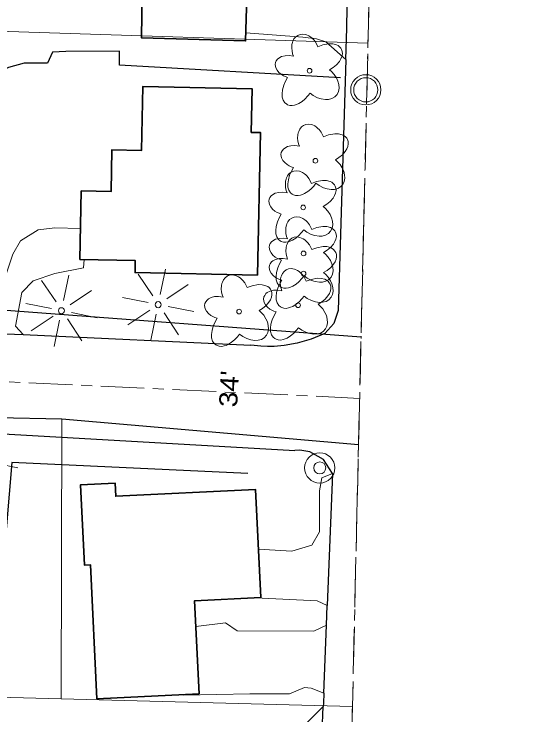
# Model space of a CAD drawing. Extents: x -861682 to -858969, y -1797841 to -1795153.
# Drawn here: x -859141.7 to -858974.4, y -1797575.9 to -1797344.4 of the extents above; entities that cross this region are included whole.
import ezdxf

# ---------------------------------------------------------------- set-up
doc = ezdxf.new("R2010")
doc.units = 0
doc.header["$LTSCALE"] = 2.4
doc.linetypes.add('DOT_DASHED', pattern=[7.7, 5, -1.2, 0.3, -1.2])
doc.linetypes.add('LONG_DASH_SHORT_DASH', pattern=[9.9, 6, -1.2, 1.5, -1.2])
for name, color, linetype, lineweight in [('10', 7, 'Continuous', 25), ('11', 7, 'Continuous', 13), ('12', 7, 'Continuous', 35), ('14', 7, 'Continuous', 25), ('17', 7, 'Continuous', 13), ('30', 7, 'Continuous', 13), ('31', 7, 'Continuous', 13), ('32', 7, 'LONG_DASH_SHORT_DASH', 13), ('36', 7, 'Continuous', 13), ('42', 7, 'Continuous', 25), ('61', 7, 'Continuous', 13)]:
    doc.layers.add(name, color=color, linetype=linetype, lineweight=lineweight)
doc.layers.add('43', color=7, linetype='Continuous')

msp = doc.modelspace()

# ---------------------------------------------------------------- linework, layer by layer
at = {"layer": '10'}
for p, q in [((-859031.959, -1797359.387), (-859034.465, -1797442.355)), ((-859150.644, -1797449.718), (-859138.672, -1797450.273)), ((-859138.672, -1797450.273), (-859063.397, -1797453.762)), ((-859160.676, -1797482.211), (-859048.845, -1797488.56)), ((-859036.441, -1797496.144), (-859038.139, -1797539.752)), ((-859040.841, -1797602.889), (-859039.445, -1797573.069))]:
    msp.add_line(p, q, dxfattribs=at)
for points in [[(-859031.959, -1797359.387), (-859031.647, -1797349.046), (-859031.317, -1797328.075), (-859030.076, -1797249.095)], [(-859034.465, -1797442.355), (-859035.905, -1797446.557), (-859038.878, -1797449.857)], [(-859038.878, -1797449.857), (-859043.482, -1797451.799), (-859048.07, -1797453.13), (-859052.41, -1797453.888), (-859055.704, -1797454.154), (-859057.908, -1797454.187), (-859060.11, -1797454.104), (-859063.397, -1797453.762)], [(-859036.441, -1797496.144), (-859039.41, -1797491.565), (-859043.901, -1797488.956), (-859047.157, -1797488.451), (-859048.845, -1797488.56)], [(-859039.268, -1797568.71), (-859038.391, -1797546.199), (-859038.139, -1797539.752)], [(-859039.268, -1797568.71), (-859039.398, -1797572.048), (-859039.445, -1797573.069)]]:
    msp.add_lwpolyline(points, dxfattribs=at)
at = {"layer": '11'}
for points in [[(-859065.049, -1797350.603), (-859046.217, -1797351.984), (-859041.666, -1797352.583), (-859038.606, -1797353.6), (-859031.959, -1797359.387)], [(-859119.67, -1797415.266), (-859128.165, -1797415.055), (-859133.683, -1797415.671), (-859139.516, -1797419.326), (-859142.077, -1797423.661), (-859144.873, -1797432.314), (-859147.655, -1797444.888), (-859150.644, -1797449.718)], [(-859118.462, -1797425.472), (-859118.655, -1797428.258), (-859128.166, -1797430.062), (-859135.329, -1797432.552), (-859139.035, -1797436.338), (-859141.126, -1797447.52), (-859138.672, -1797450.273)], [(-859060.863, -1797521.16), (-859049.801, -1797521.842), (-859043.273, -1797519.823), (-859040.739, -1797515.423), (-859040.666, -1797501.822), (-859039.896, -1797497.6), (-859036.441, -1797496.144)], [(-859061.99, -1797537.199), (-859041.503, -1797538.157), (-859038.139, -1797539.752)], [(-859081.578, -1797546.666), (-859071.713, -1797545.472), (-859067.862, -1797548.131), (-859042.601, -1797548.221), (-859038.391, -1797546.199)], [(-859085.546, -1797569.344), (-859063.761, -1797568.966), (-859050.597, -1797568.885), (-859045.596, -1797566.835), (-859043.41, -1797567.034), (-859039.268, -1797568.71)], [(-859309.938, -1797594.48), (-859309.62, -1797592.433), (-859289.953, -1797586.603), (-859281.507, -1797585.021), (-859271.667, -1797583.556), (-859251.167, -1797579.721), (-859236.104, -1797579.853), (-859215.218, -1797579.069), (-859192.063, -1797577.66), (-859174.024, -1797577.051), (-859160.73, -1797577.456), (-859109.405, -1797580.619), (-859083.978, -1797581.644), (-859068.807, -1797581.049), (-859054.386, -1797580.217), (-859044.812, -1797578.418), (-859039.445, -1797573.069)]]:
    msp.add_lwpolyline(points, dxfattribs=at)
at = {"layer": '12'}
for points in [[(-859051.474, -1797316.259), (-859063.256, -1797272.71), (-859087.25, -1797279.202), (-859086.157, -1797283.24), (-859122.212, -1797292.999), (-859111.518, -1797332.511), (-859099.235, -1797329.186), (-859099.5, -1797352.252), (-859065.127, -1797353.254), (-859064.383, -1797327.746), (-859085.787, -1797327.122), (-859085.724, -1797325.529)], [(-859061.133, -1797430.656), (-859060.143, -1797383.561), (-859063.248, -1797383.496), (-859062.946, -1797369.051), (-859099.061, -1797368.296), (-859099.503, -1797389.42), (-859109.291, -1797389.215), (-859109.58, -1797403.01), (-859119.41, -1797402.804), (-859119.884, -1797425.443), (-859101.577, -1797425.826), (-859101.66, -1797429.806)], [(-859114.254, -1797570.531), (-859116.403, -1797526.301), (-859118.358, -1797526.396), (-859119.648, -1797499.847), (-859108.241, -1797499.293), (-859108.028, -1797503.679), (-859061.821, -1797501.435), (-859060.089, -1797537.107), (-859081.991, -1797538.17), (-859080.5, -1797568.893)]]:
    msp.add_lwpolyline(points, close=True, dxfattribs=at)
at = {"layer": '14'}
for points in [[(-859033.708, -1797365.447), (-859106.737, -1797361.329), (-859106.769, -1797356.675), (-859124.551, -1797356.727), (-859128.899, -1797356.969), (-859130.59, -1797360.624), (-859138.271, -1797360.661), (-859143.419, -1797362), (-859148.483, -1797364.556), (-859153.142, -1797368.793), (-859157.373, -1797374.905), (-859159.7, -1797382.153), (-859162.796, -1797394.134), (-859163.901, -1797400.693)], [(-859064.385, -1797496.166), (-859142.416, -1797492.569), (-859148.648, -1797565.786)]]:
    msp.add_lwpolyline(points, dxfattribs=at)
at = {"layer": '17'}
for p, q in [((-859093.349, -1797437.028), (-859091.623, -1797428.628)), ((-859125.308, -1797439.034), (-859123.582, -1797430.634)), ((-859095.809, -1797437.488), (-859100.599, -1797430.36)), ((-859127.768, -1797439.494), (-859132.558, -1797432.366)), ((-859091.149, -1797438.428), (-859084.053, -1797433.688)), ((-859123.108, -1797440.434), (-859116.012, -1797435.694)), ((-859097.309, -1797439.688), (-859105.771, -1797438.014)), ((-859129.268, -1797441.694), (-859137.73, -1797440.02)), ((-859090.709, -1797440.948), (-859082.229, -1797442.672)), ((-859122.668, -1797442.954), (-859114.188, -1797444.678)), ((-859096.769, -1797442.188), (-859103.995, -1797447.044)), ((-859096.389, -1797452.148), (-859094.709, -1797443.548)), ((-859092.049, -1797443.088), (-859087.249, -1797450.302)), ((-859128.728, -1797444.194), (-859135.954, -1797449.05)), ((-859128.348, -1797454.154), (-859126.668, -1797445.554)), ((-859124.008, -1797445.094), (-859119.208, -1797452.308)), ((-859148.831, -1797492.523), (-859140.351, -1797494.247))]:
    msp.add_line(p, q, dxfattribs=at)
for points in [[(-859043.8, -1797370.522), (-859042.758, -1797371.29), (-859041.352, -1797372.012), (-859040.104, -1797372.418), (-859038.732, -1797372.614), (-859037.714, -1797372.564), (-859036.57, -1797372.274), (-859035.638, -1797371.722), (-859034.898, -1797370.934), (-859034.43, -1797369.976), (-859034.22, -1797368.898), (-859034.324, -1797367.702), (-859034.614, -1797366.53), (-859035.1, -1797365.47), (-859035.822, -1797364.326), (-859036.688, -1797363.406), (-859037.37, -1797362.794), (-859036.188, -1797362.078), (-859035.042, -1797361.13), (-859034.122, -1797360.038), (-859033.6, -1797359.182), (-859033.268, -1797358.368), (-859033.122, -1797357.552), (-859033.162, -1797356.79), (-859033.378, -1797356.11), (-859033.636, -1797355.658), (-859034.056, -1797355.184), (-859034.516, -1797354.83), (-859035.082, -1797354.54), (-859036.318, -1797354.212), (-859037.56, -1797354.178), (-859039.606, -1797354.554), (-859041.266, -1797355.192), (-859042.056, -1797353.614), (-859042.71, -1797352.8), (-859043.122, -1797352.398), (-859043.586, -1797351.998), (-859044.188, -1797351.606), (-859045.192, -1797351.174), (-859046.206, -1797351.004), (-859047.094, -1797351.104), (-859047.894, -1797351.438), (-859048.56, -1797351.924), (-859049.12, -1797352.63), (-859049.47, -1797353.386), (-859049.628, -1797353.824), (-859049.796, -1797354.5), (-859049.848, -1797355.662), (-859049.776, -1797356.56), (-859049.564, -1797357.522), (-859049.28, -1797358.328), (-859050.722, -1797358.096), (-859052.08, -1797358.146), (-859053.238, -1797358.432), (-859054.126, -1797358.93), (-859054.566, -1797359.274), (-859055, -1797359.84), (-859055.238, -1797360.374), (-859055.362, -1797361.052), (-859055.16, -1797362.156), (-859054.704, -1797362.968), (-859054.08, -1797363.73), (-859053.302, -1797364.346), (-859052.604, -1797364.77), (-859051.94, -1797365.058), (-859051.212, -1797365.296), (-859051.896, -1797366.508), (-859052.518, -1797367.876), (-859052.914, -1797369.378), (-859053.048, -1797370.712), (-859053.038, -1797371.802), (-859052.704, -1797372.82), (-859052.182, -1797373.666), (-859051.624, -1797374.102), (-859051.238, -1797374.348), (-859050.504, -1797374.572), (-859049.71, -1797374.584), (-859048.94, -1797374.46), (-859048.28, -1797374.248), (-859047.536, -1797373.926), (-859046.46, -1797373.246), (-859045.498, -1797372.46), (-859044.542, -1797371.442), (-859043.796, -1797370.532)], [(-859041.865, -1797400.271), (-859040.823, -1797401.039), (-859039.417, -1797401.761), (-859038.169, -1797402.167), (-859036.797, -1797402.363), (-859035.779, -1797402.313), (-859034.635, -1797402.023), (-859033.703, -1797401.471), (-859032.963, -1797400.683), (-859032.495, -1797399.725), (-859032.285, -1797398.647), (-859032.389, -1797397.451), (-859032.679, -1797396.279), (-859033.165, -1797395.219), (-859033.887, -1797394.075), (-859034.753, -1797393.155), (-859035.435, -1797392.543), (-859034.253, -1797391.827), (-859033.107, -1797390.879), (-859032.187, -1797389.787), (-859031.665, -1797388.931), (-859031.333, -1797388.117), (-859031.187, -1797387.301), (-859031.227, -1797386.539), (-859031.443, -1797385.859), (-859031.701, -1797385.407), (-859032.121, -1797384.933), (-859032.581, -1797384.579), (-859033.147, -1797384.289), (-859034.383, -1797383.961), (-859035.625, -1797383.927), (-859037.671, -1797384.303), (-859039.331, -1797384.941), (-859040.121, -1797383.363), (-859040.775, -1797382.549), (-859041.187, -1797382.147), (-859041.651, -1797381.747), (-859042.253, -1797381.355), (-859043.257, -1797380.923), (-859044.271, -1797380.753), (-859045.159, -1797380.853), (-859045.959, -1797381.187), (-859046.625, -1797381.673), (-859047.185, -1797382.379), (-859047.535, -1797383.135), (-859047.693, -1797383.573), (-859047.861, -1797384.249), (-859047.913, -1797385.411), (-859047.841, -1797386.309), (-859047.629, -1797387.271), (-859047.345, -1797388.077), (-859048.787, -1797387.845), (-859050.145, -1797387.895), (-859051.303, -1797388.181), (-859052.191, -1797388.679), (-859052.631, -1797389.023), (-859053.065, -1797389.589), (-859053.303, -1797390.123), (-859053.427, -1797390.801), (-859053.225, -1797391.905), (-859052.769, -1797392.717), (-859052.145, -1797393.479), (-859051.367, -1797394.095), (-859050.669, -1797394.519), (-859050.005, -1797394.807), (-859049.277, -1797395.045), (-859049.961, -1797396.257), (-859050.583, -1797397.625), (-859050.979, -1797399.127), (-859051.113, -1797400.461), (-859051.103, -1797401.551), (-859050.769, -1797402.569), (-859050.247, -1797403.415), (-859049.689, -1797403.851), (-859049.303, -1797404.097), (-859048.569, -1797404.321), (-859047.775, -1797404.333), (-859047.005, -1797404.209), (-859046.345, -1797403.997), (-859045.601, -1797403.675), (-859044.525, -1797402.995), (-859043.563, -1797402.209), (-859042.607, -1797401.191), (-859041.861, -1797400.281)], [(-859045.904, -1797415.666), (-859044.862, -1797416.434), (-859043.456, -1797417.156), (-859042.208, -1797417.562), (-859040.836, -1797417.758), (-859039.818, -1797417.708), (-859038.674, -1797417.418), (-859037.742, -1797416.866), (-859037.002, -1797416.078), (-859036.534, -1797415.12), (-859036.324, -1797414.042), (-859036.428, -1797412.846), (-859036.718, -1797411.674), (-859037.204, -1797410.614), (-859037.926, -1797409.47), (-859038.792, -1797408.55), (-859039.474, -1797407.938), (-859038.292, -1797407.222), (-859037.146, -1797406.274), (-859036.226, -1797405.182), (-859035.704, -1797404.326), (-859035.372, -1797403.512), (-859035.226, -1797402.696), (-859035.266, -1797401.934), (-859035.482, -1797401.254), (-859035.74, -1797400.802), (-859036.16, -1797400.328), (-859036.62, -1797399.974), (-859037.186, -1797399.684), (-859038.422, -1797399.356), (-859039.664, -1797399.322), (-859041.71, -1797399.698), (-859043.37, -1797400.336), (-859044.16, -1797398.758), (-859044.814, -1797397.944), (-859045.226, -1797397.542), (-859045.69, -1797397.142), (-859046.292, -1797396.75), (-859047.296, -1797396.318), (-859048.31, -1797396.148), (-859049.198, -1797396.248), (-859049.998, -1797396.582), (-859050.664, -1797397.068), (-859051.224, -1797397.774), (-859051.574, -1797398.53), (-859051.732, -1797398.968), (-859051.9, -1797399.644), (-859051.952, -1797400.806), (-859051.88, -1797401.704), (-859051.668, -1797402.666), (-859051.384, -1797403.472), (-859052.826, -1797403.24), (-859054.184, -1797403.29), (-859055.342, -1797403.576), (-859056.23, -1797404.074), (-859056.67, -1797404.418), (-859057.104, -1797404.984), (-859057.342, -1797405.518), (-859057.466, -1797406.196), (-859057.264, -1797407.3), (-859056.808, -1797408.112), (-859056.184, -1797408.874), (-859055.406, -1797409.49), (-859054.708, -1797409.914), (-859054.044, -1797410.202), (-859053.316, -1797410.44), (-859054, -1797411.652), (-859054.622, -1797413.02), (-859055.018, -1797414.522), (-859055.152, -1797415.856), (-859055.142, -1797416.946), (-859054.808, -1797417.964), (-859054.286, -1797418.81), (-859053.728, -1797419.246), (-859053.342, -1797419.492), (-859052.608, -1797419.716), (-859051.814, -1797419.728), (-859051.044, -1797419.604), (-859050.384, -1797419.392), (-859049.64, -1797419.07), (-859048.564, -1797418.39), (-859047.602, -1797417.604), (-859046.646, -1797416.586), (-859045.9, -1797415.676)], [(-859045.79, -1797430.871), (-859044.748, -1797431.639), (-859043.342, -1797432.361), (-859042.094, -1797432.767), (-859040.722, -1797432.963), (-859039.704, -1797432.913), (-859038.56, -1797432.623), (-859037.628, -1797432.071), (-859036.888, -1797431.283), (-859036.42, -1797430.325), (-859036.21, -1797429.247), (-859036.314, -1797428.051), (-859036.604, -1797426.879), (-859037.09, -1797425.819), (-859037.812, -1797424.675), (-859038.678, -1797423.755), (-859039.36, -1797423.143), (-859038.178, -1797422.427), (-859037.032, -1797421.479), (-859036.112, -1797420.387), (-859035.59, -1797419.531), (-859035.258, -1797418.717), (-859035.112, -1797417.901), (-859035.152, -1797417.139), (-859035.368, -1797416.459), (-859035.626, -1797416.007), (-859036.046, -1797415.533), (-859036.506, -1797415.179), (-859037.072, -1797414.889), (-859038.308, -1797414.561), (-859039.55, -1797414.527), (-859041.596, -1797414.903), (-859043.256, -1797415.541), (-859044.046, -1797413.963), (-859044.7, -1797413.149), (-859045.112, -1797412.747), (-859045.576, -1797412.347), (-859046.178, -1797411.955), (-859047.182, -1797411.523), (-859048.196, -1797411.353), (-859049.084, -1797411.453), (-859049.884, -1797411.787), (-859050.55, -1797412.273), (-859051.11, -1797412.979), (-859051.46, -1797413.735), (-859051.618, -1797414.173), (-859051.786, -1797414.849), (-859051.838, -1797416.011), (-859051.766, -1797416.909), (-859051.554, -1797417.871), (-859051.27, -1797418.677), (-859052.712, -1797418.445), (-859054.07, -1797418.495), (-859055.228, -1797418.781), (-859056.116, -1797419.279), (-859056.556, -1797419.623), (-859056.99, -1797420.189), (-859057.228, -1797420.723), (-859057.352, -1797421.401), (-859057.15, -1797422.505), (-859056.694, -1797423.317), (-859056.07, -1797424.079), (-859055.292, -1797424.695), (-859054.594, -1797425.119), (-859053.93, -1797425.407), (-859053.202, -1797425.645), (-859053.886, -1797426.857), (-859054.508, -1797428.225), (-859054.904, -1797429.727), (-859055.038, -1797431.061), (-859055.028, -1797432.151), (-859054.694, -1797433.169), (-859054.172, -1797434.015), (-859053.614, -1797434.451), (-859053.228, -1797434.697), (-859052.494, -1797434.921), (-859051.7, -1797434.933), (-859050.93, -1797434.809), (-859050.27, -1797434.597), (-859049.526, -1797434.275), (-859048.45, -1797433.595), (-859047.488, -1797432.809), (-859046.532, -1797431.791), (-859045.786, -1797430.881)], [(-859045.754, -1797437.533), (-859044.712, -1797438.301), (-859043.306, -1797439.023), (-859042.058, -1797439.429), (-859040.686, -1797439.625), (-859039.668, -1797439.575), (-859038.524, -1797439.285), (-859037.592, -1797438.733), (-859036.852, -1797437.945), (-859036.384, -1797436.987), (-859036.174, -1797435.909), (-859036.278, -1797434.713), (-859036.568, -1797433.541), (-859037.054, -1797432.481), (-859037.776, -1797431.337), (-859038.642, -1797430.417), (-859039.324, -1797429.805), (-859038.142, -1797429.089), (-859036.996, -1797428.141), (-859036.076, -1797427.049), (-859035.554, -1797426.193), (-859035.222, -1797425.379), (-859035.076, -1797424.563), (-859035.116, -1797423.801), (-859035.332, -1797423.121), (-859035.59, -1797422.669), (-859036.01, -1797422.195), (-859036.47, -1797421.841), (-859037.036, -1797421.551), (-859038.272, -1797421.223), (-859039.514, -1797421.189), (-859041.56, -1797421.565), (-859043.22, -1797422.203), (-859044.01, -1797420.625), (-859044.664, -1797419.811), (-859045.076, -1797419.409), (-859045.54, -1797419.009), (-859046.142, -1797418.617), (-859047.146, -1797418.185), (-859048.16, -1797418.015), (-859049.048, -1797418.115), (-859049.848, -1797418.449), (-859050.514, -1797418.935), (-859051.074, -1797419.641), (-859051.424, -1797420.397), (-859051.582, -1797420.835), (-859051.75, -1797421.511), (-859051.802, -1797422.673), (-859051.73, -1797423.571), (-859051.518, -1797424.533), (-859051.234, -1797425.339), (-859052.676, -1797425.107), (-859054.034, -1797425.157), (-859055.192, -1797425.443), (-859056.08, -1797425.941), (-859056.52, -1797426.285), (-859056.954, -1797426.851), (-859057.192, -1797427.385), (-859057.316, -1797428.063), (-859057.114, -1797429.167), (-859056.658, -1797429.979), (-859056.034, -1797430.741), (-859055.256, -1797431.357), (-859054.558, -1797431.781), (-859053.894, -1797432.069), (-859053.166, -1797432.307), (-859053.85, -1797433.519), (-859054.472, -1797434.887), (-859054.868, -1797436.389), (-859055.002, -1797437.723), (-859054.992, -1797438.813), (-859054.658, -1797439.831), (-859054.136, -1797440.677), (-859053.578, -1797441.113), (-859053.192, -1797441.359), (-859052.458, -1797441.583), (-859051.664, -1797441.595), (-859050.894, -1797441.471), (-859050.234, -1797441.259), (-859049.49, -1797440.937), (-859048.414, -1797440.257), (-859047.452, -1797439.471), (-859046.496, -1797438.453), (-859045.75, -1797437.543)], [(-859047.61, -1797447.997), (-859046.568, -1797448.765), (-859045.162, -1797449.487), (-859043.914, -1797449.893), (-859042.542, -1797450.089), (-859041.524, -1797450.039), (-859040.38, -1797449.749), (-859039.448, -1797449.197), (-859038.708, -1797448.409), (-859038.24, -1797447.451), (-859038.03, -1797446.373), (-859038.134, -1797445.177), (-859038.424, -1797444.005), (-859038.91, -1797442.945), (-859039.632, -1797441.801), (-859040.498, -1797440.881), (-859041.18, -1797440.269), (-859039.998, -1797439.553), (-859038.852, -1797438.605), (-859037.932, -1797437.513), (-859037.41, -1797436.657), (-859037.078, -1797435.843), (-859036.932, -1797435.027), (-859036.972, -1797434.265), (-859037.188, -1797433.585), (-859037.446, -1797433.133), (-859037.866, -1797432.659), (-859038.326, -1797432.305), (-859038.892, -1797432.015), (-859040.128, -1797431.687), (-859041.37, -1797431.653), (-859043.416, -1797432.029), (-859045.076, -1797432.667), (-859045.866, -1797431.089), (-859046.52, -1797430.275), (-859046.932, -1797429.873), (-859047.396, -1797429.473), (-859047.998, -1797429.081), (-859049.002, -1797428.649), (-859050.016, -1797428.479), (-859050.904, -1797428.579), (-859051.704, -1797428.913), (-859052.37, -1797429.399), (-859052.93, -1797430.105), (-859053.28, -1797430.861), (-859053.438, -1797431.299), (-859053.606, -1797431.975), (-859053.658, -1797433.137), (-859053.586, -1797434.035), (-859053.374, -1797434.997), (-859053.09, -1797435.803), (-859054.532, -1797435.571), (-859055.89, -1797435.621), (-859057.048, -1797435.907), (-859057.936, -1797436.405), (-859058.376, -1797436.749), (-859058.81, -1797437.315), (-859059.048, -1797437.849), (-859059.172, -1797438.527), (-859058.97, -1797439.631), (-859058.514, -1797440.443), (-859057.89, -1797441.205), (-859057.112, -1797441.821), (-859056.414, -1797442.245), (-859055.75, -1797442.533), (-859055.022, -1797442.771), (-859055.706, -1797443.983), (-859056.328, -1797445.351), (-859056.724, -1797446.853), (-859056.858, -1797448.187), (-859056.848, -1797449.277), (-859056.514, -1797450.295), (-859055.992, -1797451.141), (-859055.434, -1797451.577), (-859055.048, -1797451.823), (-859054.314, -1797452.047), (-859053.52, -1797452.059), (-859052.75, -1797451.935), (-859052.09, -1797451.723), (-859051.346, -1797451.401), (-859050.27, -1797450.721), (-859049.308, -1797449.935), (-859048.352, -1797448.917), (-859047.606, -1797448.007)], [(-859067.099, -1797450.092), (-859066.057, -1797450.86), (-859064.651, -1797451.582), (-859063.403, -1797451.988), (-859062.031, -1797452.184), (-859061.013, -1797452.134), (-859059.869, -1797451.844), (-859058.937, -1797451.292), (-859058.197, -1797450.504), (-859057.729, -1797449.546), (-859057.519, -1797448.468), (-859057.623, -1797447.272), (-859057.913, -1797446.1), (-859058.399, -1797445.04), (-859059.121, -1797443.896), (-859059.987, -1797442.976), (-859060.669, -1797442.364), (-859059.487, -1797441.648), (-859058.341, -1797440.7), (-859057.421, -1797439.608), (-859056.899, -1797438.752), (-859056.567, -1797437.938), (-859056.421, -1797437.122), (-859056.461, -1797436.36), (-859056.677, -1797435.68), (-859056.935, -1797435.228), (-859057.355, -1797434.754), (-859057.815, -1797434.4), (-859058.381, -1797434.11), (-859059.617, -1797433.782), (-859060.859, -1797433.748), (-859062.905, -1797434.124), (-859064.565, -1797434.762), (-859065.355, -1797433.184), (-859066.009, -1797432.37), (-859066.421, -1797431.968), (-859066.885, -1797431.568), (-859067.487, -1797431.176), (-859068.491, -1797430.744), (-859069.505, -1797430.574), (-859070.393, -1797430.674), (-859071.193, -1797431.008), (-859071.859, -1797431.494), (-859072.419, -1797432.2), (-859072.769, -1797432.956), (-859072.927, -1797433.394), (-859073.095, -1797434.07), (-859073.147, -1797435.232), (-859073.075, -1797436.13), (-859072.863, -1797437.092), (-859072.579, -1797437.898), (-859074.021, -1797437.666), (-859075.379, -1797437.716), (-859076.537, -1797438.002), (-859077.425, -1797438.5), (-859077.865, -1797438.844), (-859078.299, -1797439.41), (-859078.537, -1797439.944), (-859078.661, -1797440.622), (-859078.459, -1797441.726), (-859078.003, -1797442.538), (-859077.379, -1797443.3), (-859076.601, -1797443.916), (-859075.903, -1797444.34), (-859075.239, -1797444.628), (-859074.511, -1797444.866), (-859075.195, -1797446.078), (-859075.817, -1797447.446), (-859076.213, -1797448.948), (-859076.347, -1797450.282), (-859076.337, -1797451.372), (-859076.003, -1797452.39), (-859075.481, -1797453.236), (-859074.923, -1797453.672), (-859074.537, -1797453.918), (-859073.803, -1797454.142), (-859073.009, -1797454.154), (-859072.239, -1797454.03), (-859071.579, -1797453.818), (-859070.835, -1797453.496), (-859069.759, -1797452.816), (-859068.797, -1797452.03), (-859067.841, -1797451.012), (-859067.095, -1797450.102)]]:
    msp.add_lwpolyline(points, dxfattribs=at)
for centre, radius in [((-859043.98, -1797363.11), 0.773), ((-859042.045, -1797392.859), 0.773), ((-859046.084, -1797408.254), 0.773), ((-859045.97, -1797423.459), 0.773), ((-859045.934, -1797430.121), 0.773), ((-859125.968, -1797442.394), 1), ((-859094.009, -1797440.388), 1), ((-859047.79, -1797440.585), 0.773), ((-859067.279, -1797442.68), 0.773)]:
    msp.add_circle(centre, radius, dxfattribs=at)
at = {"layer": '30'}
for p, q in [((-859024.68, -1797354.059), (-859151.786, -1797349.906)), ((-859125.863, -1797478.159), (-859126.119, -1797570.529)), ((-859267.682, -1797567.05), (-859126.119, -1797570.529)), ((-859029.782, -1797573.149), (-859126.119, -1797570.529))]:
    msp.add_line(p, q, dxfattribs=at)
at = {"layer": '31'}
for radius in [5, 2]:
    msp.add_circle((-859040.606, -1797494.307), radius, dxfattribs=at)
at = {"layer": '32'}
for p, q in [((-859002.083, -1796383.657), (-859035.9, -1797835.881)), ((-859027.411, -1797471.328), (-859307.057, -1797458.229))]:
    msp.add_line(p, q, dxfattribs=at)
at = {"layer": '36'}
for radius in [5, 4]:
    msp.add_circle((-859025.388, -1797369.418), radius, dxfattribs=at)
at = {"layer": '42'}
for p, q in [((-859026.94, -1797451.109), (-859152.641, -1797441.698)), ((-859125.863, -1797478.159), (-859250.133, -1797475.623)), ((-859027.769, -1797486.7), (-859125.863, -1797478.159))]:
    msp.add_line(p, q, dxfattribs=at)
at = {"layer": '61', "linetype": 'DOT_DASHED'}
msp.add_line((-859035.9, -1797835.881), (-858974.429, -1795196.105), dxfattribs=at)

# ---------------------------------------------------------------- texts
at = {"layer": '43', "width": 1.15}
msp.add_text("34'", height=6, rotation=86.855, dxfattribs=at).set_placement((-859067.937, -1797474.376))

doc.saveas('drawing.dxf')
